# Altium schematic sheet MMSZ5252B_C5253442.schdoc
size 127 x 101 mm
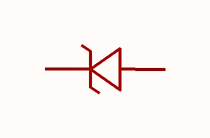
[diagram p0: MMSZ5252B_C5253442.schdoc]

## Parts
D?  mmsz5252b_c5253442  [SOD-123_L2.7-W1.6-LS3.7-RD]  (value not drawn)

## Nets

Not connected (* = marked no-connect by the designer): D? 1(C) 2(A)

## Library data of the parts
D? = mmsz5252b_c5253442: 二极管配置:1个独立式;稳压值(标称值):24V;稳压值(范围):22.8V~25.2V;耗散功率(Pd):500mW;; Manufacturer: MDD(辰达半导体); AddInBom: yes; ModelId: ad7e39f9e5534b3c96ffdc5532ebb493; ModelName: SOD-123_L2.7-W1.6-H1.4-LS3.7; ModelTransform: 146.026,62.992,0,180,0,0,0.0005,0,0; Diode Configuration: 1个独立式; Zener Voltage(Nom): 24V; Reverse Leakage Current (Ir): 100nA@18V; Pd - Power Dissipation: 500mW; Impedance(Zzt): 33Ω; Impedance(Zzk): 600Ω; Tolerance: ±5%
